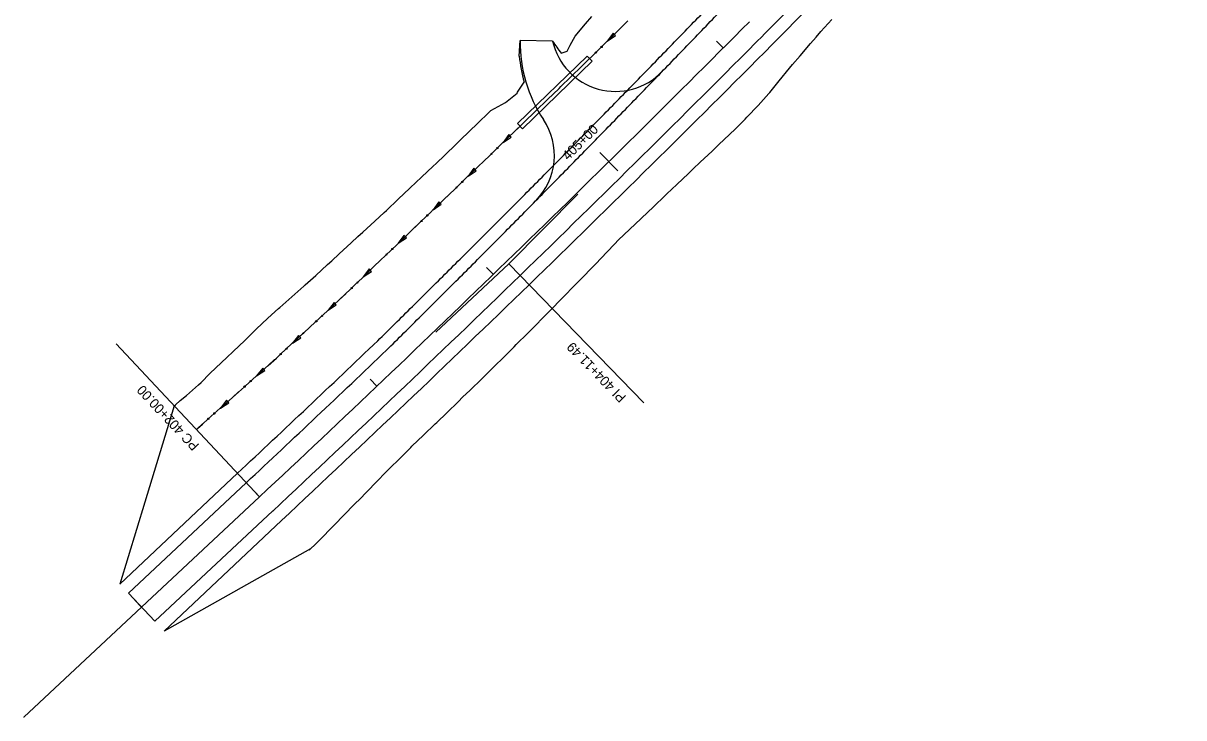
# Model space of a CAD drawing. Extents: x 1375694 to 1433473, y 1931050 to 1967991.
# Drawn here: x 1428574 to 1429293, y 1963362 to 1963792 of the extents above; entities that cross this region are included whole.
import ezdxf

# ---------------------------------------------------------------- set-up
doc = ezdxf.new("R2010")
doc.units = 0
for name, color, linetype in [('62', 7, 'Continuous'), ('R_Drainage', 7, 'Continuous'), ('R_Horz Alg', 7, 'Continuous'), ('R_Horz Alg Annot', 7, 'Continuous'), ('R_Proposed Const Limits', 7, 'Continuous'), ('R_Proposed Road', 7, 'Continuous')]:
    doc.layers.add(name, color=color, linetype=linetype)

msp = doc.modelspace()

# ---------------------------------------------------------------- linework, layer by layer
at = {"layer": '62'}
for p, q in [((1428939.23, 1963786.03), (1428935.7, 1963781.06)), ((1428935.7, 1963781.06), (1428940.72, 1963784.52)), ((1428940.72, 1963784.52), (1428939.23, 1963786.03)), ((1428874.69, 1963723.16), (1428871.1, 1963718.23)), ((1428871.1, 1963718.23), (1428876.16, 1963721.63)), ((1428876.16, 1963721.63), (1428874.69, 1963723.16)), ((1428853.08, 1963702.29), (1428849.49, 1963697.37)), ((1428849.49, 1963697.37), (1428854.55, 1963700.77)), ((1428854.55, 1963700.77), (1428853.08, 1963702.29)), ((1428831.43, 1963681.47), (1428827.84, 1963676.55)), ((1428832.9, 1963679.95), (1428831.43, 1963681.47)), ((1428827.84, 1963676.55), (1428832.9, 1963679.95)), ((1428809.77, 1963660.66), (1428806.17, 1963655.75)), ((1428811.23, 1963659.14), (1428809.77, 1963660.66)), ((1428806.17, 1963655.75), (1428811.23, 1963659.14)), ((1428788.1, 1963639.86), (1428784.51, 1963634.93)), ((1428784.51, 1963634.93), (1428789.57, 1963638.33)), ((1428789.57, 1963638.33), (1428788.1, 1963639.86)), ((1428766.42, 1963619.09), (1428762.75, 1963614.23)), ((1428762.75, 1963614.23), (1428767.86, 1963617.55)), ((1428767.86, 1963617.55), (1428766.42, 1963619.09)), ((1428744.38, 1963598.69), (1428740.69, 1963593.84)), ((1428740.69, 1963593.84), (1428745.82, 1963597.13)), ((1428745.82, 1963597.13), (1428744.38, 1963598.69)), ((1428722.25, 1963578.41), (1428718.48, 1963573.62)), ((1428718.48, 1963573.62), (1428723.66, 1963576.83)), ((1428723.66, 1963576.83), (1428722.25, 1963578.41)), ((1428699.83, 1963558.42), (1428696.04, 1963553.65)), ((1428696.04, 1963553.65), (1428701.23, 1963556.84)), ((1428701.23, 1963556.84), (1428699.83, 1963558.42))]:
    msp.add_line(p, q, dxfattribs=at)
for points in [[(1428681.2, 1963540.32), (1428681.93, 1963540.99), (1428684.88, 1963543.66), (1428688.57, 1963547), (1428696.01, 1963553.62), (1428697.69, 1963555.11), (1428703.45, 1963560.23), (1428710.89, 1963566.85), (1428714.24, 1963569.84), (1428718.31, 1963573.48), (1428725.74, 1963580.11), (1428730.73, 1963584.65), (1428733.09, 1963586.82), (1428740.4, 1963593.57), (1428747.01, 1963599.67), (1428747.71, 1963600.32), (1428755.02, 1963607.08), (1428762.32, 1963613.84), (1428763.27, 1963614.72), (1428769.61, 1963620.62), (1428776.79, 1963627.51), (1428779.35, 1963629.96), (1428783.97, 1963634.41), (1428791.14, 1963641.31), (1428795.3, 1963645.33), (1428798.3, 1963648.22), (1428805.49, 1963655.1), (1428811.3, 1963660.66), (1428812.68, 1963661.98), (1428819.86, 1963668.87), (1428827.03, 1963675.77), (1428827.28, 1963676.01), (1428834.2, 1963682.67), (1428841.38, 1963689.57), (1428843.25, 1963691.36), (1428848.56, 1963696.46), (1428855.72, 1963703.37), (1428859.21, 1963706.73), (1428862.88, 1963710.29), (1428870.04, 1963717.2), (1428875.14, 1963722.12), (1428877.21, 1963724.11), (1428884.37, 1963731.01), (1428891.09, 1963737.5), (1428891.53, 1963737.93), (1428898.69, 1963744.85), (1428905.84, 1963751.77), (1428907.01, 1963752.91), (1428912.96, 1963758.72), (1428920.07, 1963765.69), (1428922.84, 1963768.41), (1428927.17, 1963772.66), (1428934.27, 1963779.64), (1428938.63, 1963783.95), (1428941.35, 1963786.63), (1428948.44, 1963793.63)], [(1428946.38, 1963791.6), (1428941.35, 1963786.63), (1428938.63, 1963783.95), (1428935.7, 1963781.06)], [(1428946.41, 1963791.62), (1428946.38, 1963791.6)], [(1428925.01, 1963770.54), (1428924.98, 1963770.51)], [(1428881.91, 1963728.64), (1428877.21, 1963724.11), (1428875.14, 1963722.12), (1428871.1, 1963718.23)], [(1428881.93, 1963728.66), (1428881.91, 1963728.64)], [(1428860.29, 1963707.78), (1428859.21, 1963706.73), (1428855.72, 1963703.37), (1428849.49, 1963697.37)], [(1428860.32, 1963707.81), (1428860.29, 1963707.78)], [(1428838.65, 1963686.95), (1428834.2, 1963682.67), (1428827.84, 1963676.55)], [(1428838.68, 1963686.97), (1428838.65, 1963686.95)], [(1428817, 1963666.13), (1428812.68, 1963661.98), (1428811.3, 1963660.66), (1428806.17, 1963655.75)], [(1428817.03, 1963666.16), (1428817, 1963666.13)], [(1428795.31, 1963645.34), (1428795.3, 1963645.33), (1428791.14, 1963641.31), (1428784.51, 1963634.93)], [(1428795.34, 1963645.37), (1428795.31, 1963645.34)], [(1428773.67, 1963624.51), (1428769.61, 1963620.62), (1428763.27, 1963614.72), (1428762.75, 1963614.23)], [(1428773.7, 1963624.54), (1428773.67, 1963624.51)], [(1428751.71, 1963604.02), (1428747.71, 1963600.32), (1428747.01, 1963599.67), (1428740.69, 1963593.84)], [(1428751.74, 1963604.04), (1428751.71, 1963604.02)], [(1428729.63, 1963583.65), (1428725.74, 1963580.11), (1428718.48, 1963573.62)], [(1428729.66, 1963583.68), (1428729.63, 1963583.65)], [(1428707.25, 1963563.62), (1428703.45, 1963560.23), (1428697.69, 1963555.11), (1428696.04, 1963553.65)], [(1428707.28, 1963563.64), (1428707.25, 1963563.62)], [(1428684.84, 1963543.62), (1428681.93, 1963540.99), (1428681.2, 1963540.32)], [(1428684.87, 1963543.65), (1428684.84, 1963543.62)]]:
    msp.add_lwpolyline(points, dxfattribs=at)
for centre in [(1428932.16, 1963777.52), (1428928.59, 1963774.01), (1428863.93, 1963711.24), (1428867.53, 1963714.73), (1428842.3, 1963690.4), (1428845.91, 1963693.87), (1428820.65, 1963669.58), (1428824.26, 1963673.05), (1428798.95, 1963648.8), (1428802.58, 1963652.26), (1428780.93, 1963631.44), (1428777.32, 1963627.96), (1428759.1, 1963610.81), (1428755.42, 1963607.4), (1428737.04, 1963590.42), (1428733.36, 1963587.02), (1428711.03, 1963566.93), (1428714.77, 1963570.26), (1428688.58, 1963546.97), (1428692.33, 1963550.3)]:
    msp.add_circle(centre, 0.375, dxfattribs=at)
at = {"layer": 'R_Drainage'}
for p, q in [((1428923.13, 1963771.85), (1428880.06, 1963729.98)), ((1428883.19, 1963726.75), (1428926.27, 1963768.62)), ((1428926.27, 1963768.62), (1428923.13, 1963771.85)), ((1428880.06, 1963729.98), (1428883.19, 1963726.75))]:
    msp.add_line(p, q, dxfattribs=at)
at = {"layer": 'R_Horz Alg'}
msp.add_line((1428574.21, 1963361.93), (1428720.26, 1963498.57), dxfattribs=at)
msp.add_arc((1420891.39, 1971866.43), 11459.16, 313.094012, 315.208721, dxfattribs=at)
at = {"layer": 'R_Horz Alg Annot'}
for p in [(1428917.52, 1963686.2), (1428829.49, 1963600.77)]:
    msp.add_line(p, (1428874.7, 1963643.06), dxfattribs=at)
for points in [[(1429003.27, 1963781.13), (1429007.52, 1963776.89)], [(1428931, 1963712.07), (1428942.24, 1963700.68)], [(1428860.93, 1963640.79), (1428865.11, 1963636.48)], [(1428874.7, 1963643.06), (1428958.29, 1963556.96)], [(1428720.26, 1963498.57), (1428631.44, 1963593.5)], [(1428788.85, 1963571.55), (1428792.98, 1963567.21)], [(1428716.16, 1963502.95), (1428720.26, 1963498.57)], [(1428643.14, 1963434.63), (1428647.24, 1963430.25)]]:
    msp.add_lwpolyline(points, dxfattribs=at)
at = {"layer": 'R_Proposed Const Limits'}
for p, q in [((1428881.15, 1963771.86), (1428881.8, 1963781.45)), ((1428667.51, 1963554.95), (1428649.3, 1963495.22)), ((1428649.3, 1963495.22), (1428633.85, 1963444.55)), ((1428751.85, 1963466.28), (1428661.28, 1963415.24))]:
    msp.add_line(p, q, dxfattribs=at)
for points in [[(1428907.2, 1963773.61), (1428910.93, 1963774.91), (1428912.64, 1963778.7), (1428915.71, 1963784.2), (1428922.14, 1963791.83), (1428926.19, 1963796.45)], [(1428751.13, 1963465.58), (1428751.85, 1963466.28), (1428754.73, 1963469.08), (1428758.31, 1963472.59), (1428765.32, 1963479.79), (1428766.92, 1963481.41), (1428772.37, 1963486.95), (1428779.35, 1963494.18), (1428782.53, 1963497.43), (1428786.37, 1963501.37), (1428793.34, 1963508.61), (1428798.14, 1963513.44), (1428800.43, 1963515.72), (1428807.51, 1963522.84), (1428813.94, 1963529.25), (1428814.64, 1963529.91), (1428821.93, 1963536.8), (1428829.11, 1963543.81), (1428830.03, 1963544.74), (1428836.35, 1963550.77), (1428843.56, 1963557.75), (1428846.08, 1963560.29), (1428850.73, 1963564.78), (1428857.95, 1963571.74), (1428862.06, 1963575.89), (1428865.05, 1963578.85), (1428872.22, 1963585.87), (1428877.99, 1963591.57), (1428879.34, 1963592.94), (1428886.39, 1963600.09), (1428893.51, 1963607.16), (1428893.75, 1963607.4), (1428900.54, 1963614.33), (1428907.55, 1963621.51), (1428909.4, 1963623.36), (1428914.58, 1963628.68), (1428921.55, 1963635.9), (1428924.95, 1963639.41), (1428928.55, 1963643.1), (1428935.49, 1963650.35), (1428940.42, 1963655.53), (1428942.4, 1963657.63), (1428949.71, 1963664.51), (1428956.52, 1963671.02), (1428956.97, 1963671.44), (1428964.23, 1963678.37), (1428971.48, 1963685.31), (1428972.67, 1963686.44), (1428978.78, 1963692.2), (1428986.06, 1963699.11), (1428988.87, 1963701.84), (1428993.32, 1963706.04), (1429000.58, 1963712.97), (1429005.08, 1963717.21), (1429007.84, 1963719.9), (1429015.13, 1963726.8), (1429021.05, 1963732.83), (1429022.16, 1963733.97), (1429029.18, 1963741.14), (1429035.83, 1963748.68), (1429036.27, 1963749.21), (1429042.13, 1963756.56), (1429048.59, 1963764.29), (1429050.45, 1963766.6), (1429055.06, 1963771.94), (1429061.46, 1963779.63), (1429064.97, 1963783.51), (1429068.03, 1963787.16), (1429074.7, 1963794.59)], [(1428667.51, 1963554.95), (1428668.19, 1963555.68), (1428671.18, 1963558.29), (1428675.04, 1963561.44), (1428682.49, 1963568.02), (1428684.13, 1963569.55), (1428689.59, 1963574.97), (1428696.82, 1963581.78), (1428700.02, 1963584.93), (1428703.91, 1963588.74), (1428711.18, 1963595.5), (1428715.93, 1963600.28), (1428718.25, 1963602.48), (1428725.43, 1963609.35), (1428732.05, 1963615.42), (1428732.77, 1963616.05), (1428740.2, 1963622.65), (1428747.64, 1963629.24), (1428748.61, 1963630.09), (1428755.07, 1963635.84), (1428762.38, 1963642.57), (1428764.99, 1963644.96), (1428769.72, 1963649.27), (1428777.02, 1963656.01), (1428781.26, 1963659.94), (1428784.32, 1963662.75), (1428791.67, 1963669.44), (1428797.59, 1963674.87), (1428798.99, 1963676.16), (1428806.17, 1963683.03), (1428813.39, 1963689.85), (1428813.64, 1963690.08), (1428820.58, 1963696.71), (1428827.76, 1963703.58), (1428829.65, 1963705.34), (1428834.99, 1963710.4), (1428842.12, 1963717.31), (1428845.6, 1963720.66), (1428849.32, 1963724.16), (1428856.43, 1963731.1), (1428861.5, 1963736.04), (1428863.58, 1963738), (1428872.62, 1963742.98), (1428879.91, 1963748.87), (1428880.08, 1963749.56), (1428884.23, 1963755.68)]]:
    msp.add_lwpolyline(points, dxfattribs=at)
for centre, radius, start, end in [((1428966.03, 1963821.47), 75.84, 212.12626, 219.13219), ((1428966.79, 1963779.76), 86, 185.26915, 196.26307)]:
    msp.add_arc(centre, radius, start, end, dxfattribs=at)
at = {"layer": 'R_Proposed Road'}
for p, q in [((1428881.8, 1963781.45), (1428881.81, 1963781.54)), ((1428901.8, 1963781.14), (1428881.81, 1963781.54)), ((1428706.6, 1963513.17), (1428633.85, 1963444.55)), ((1428712.06, 1963507.33), (1428639.09, 1963438.96)), ((1428728.46, 1963489.81), (1428655.47, 1963421.45)), ((1428661.28, 1963415.24), (1428733.92, 1963483.96)), ((1428639.09, 1963438.96), (1428655.47, 1963421.45))]:
    msp.add_line(p, q, dxfattribs=at)
for centre, radius, start, end in [((1437156.01, 1955719.88), 11447.16, 133.424411, 135.208721), ((1437156.01, 1955719.88), 11439.16, 133.424411, 135.208721), ((1420891.39, 1971866.43), 11471.16, 313.094012, 315.208721), ((1420891.39, 1971866.43), 11479.16, 313.094012, 315.208721), ((1428966.79, 1963779.76), 85, 178.85836, 213.80396), ((1428940.82, 1963789.96), 40, 192.73917, 316.11922), ((1428862.92, 1963710.22), 40, 315.39035, 33.80396), ((1420891.39, 1971866.43), 11439.16, 313.094012, 313.693012), ((1420891.39, 1971866.43), 11447.16, 313.094012, 313.693012)]:
    msp.add_arc(centre, radius, start, end, dxfattribs=at)
for points in [[(1428793.5, 1963595.33), (1428797.09, 1963598.87), (1428804.27, 1963605.96), (1428815.03, 1963616.6), (1428825.78, 1963627.25), (1428836.51, 1963637.92), (1428847.23, 1963648.6), (1428857.93, 1963659.29), (1428868.62, 1963670), (1428879.29, 1963680.72), (1428889.95, 1963691.46), (1428900.6, 1963702.21), (1428911.23, 1963712.98), (1428921.84, 1963723.76), (1428932.45, 1963734.55), (1428943.03, 1963745.35), (1428953.61, 1963756.17), (1428964.17, 1963767.01), (1428974.71, 1963777.85), (1428985.24, 1963788.72), (1428995.75, 1963799.59), (1429002.75, 1963806.85), (1429006.25, 1963810.48)], [(1428799.02, 1963589.55), (1428802.61, 1963593.1), (1428809.78, 1963600.21), (1428820.51, 1963610.89), (1428831.23, 1963621.58), (1428841.94, 1963632.29), (1428852.63, 1963643.01), (1428863.31, 1963653.75), (1428873.97, 1963664.5), (1428884.62, 1963675.26), (1428895.26, 1963686.04), (1428905.88, 1963696.83), (1428916.48, 1963707.63), (1428927.08, 1963718.45), (1428937.65, 1963729.28), (1428948.21, 1963740.13), (1428958.76, 1963750.99), (1428969.29, 1963761.86), (1428979.81, 1963772.75), (1428990.32, 1963783.65), (1429000.8, 1963794.56), (1429007.79, 1963801.85), (1429011.28, 1963805.49)]]:
    msp.add_open_spline(points, degree=3, dxfattribs=at)

# ---------------------------------------------------------------- texts
at = {"layer": 'R_Horz Alg'}
for p in [(1428720.29, 1963497.91), (1428574.24, 1963361.27)]:
    msp.add_text('+', height=1, rotation=43.09401, dxfattribs=at).set_placement(p)
at = {"layer": 'R_Horz Alg Annot'}
for s, rotation, p in [('405+00', 44.59401, (1428911.42, 1963706.8)), ('PI 404+11.49', 134.15137, (1428947.73, 1963560.65)), ('PC 402+00.00', 133.09401, (1428683.33, 1963530.72))]:
    msp.add_text(s, height=6, rotation=rotation, dxfattribs=at).set_placement(p)

doc.saveas('drawing.dxf')
